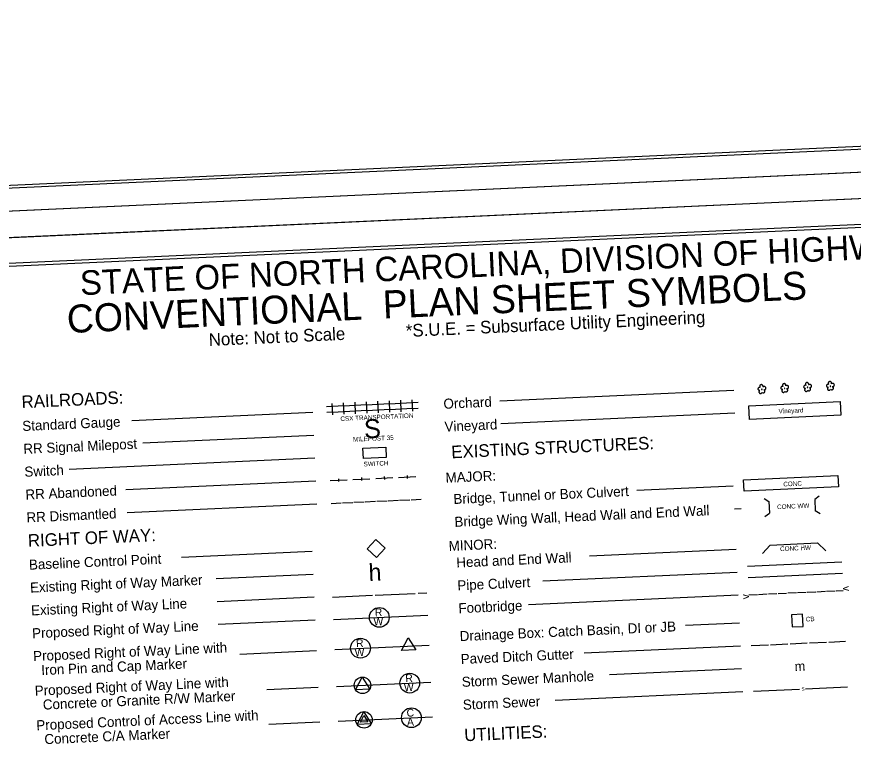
# Model space of a CAD drawing. Extents: x 1190067 to 1192950, y 891516 to 893460.
# Drawn here: x 1191359.1 to 1191651.7, y 891789.2 to 892043.5 of the extents above; entities that cross this region are included whole.
import ezdxf

# ---------------------------------------------------------------- set-up
doc = ezdxf.new("R2010")
doc.units = 0
for name, color, linetype in [('Prop Dimension Text', 7, 'Continuous'), ('Sheet Cutting Line CELL', 7, 'Continuous'), ('Sheet Plan CELL', 7, 'Continuous'), ('Sheet Plot Border Inside CELL', 7, 'Continuous'), ('Sheet Plot Border Outside CELL', 7, 'Continuous'), ('Sheet Symbology CELL', 7, 'Continuous')]:
    doc.layers.add(name, color=color, linetype=linetype)

# ---------------------------------------------------------------- blocks, each defined once
blk = doc.blocks.new('PRRM')
at = {"layer": 'Sheet Symbology CELL'}
blk.add_line((0, 0), (0, 0), dxfattribs=at)
blk.add_lwpolyline([(-0.125, -0.072), (0, 0.144), (0.125, -0.072)], close=True, dxfattribs=at)
blk = doc.blocks.new('RWCON')
at = {"layer": 'Sheet Symbology CELL'}
blk.add_line((0, 0), (0, 0), dxfattribs=at)
blk.add_lwpolyline([(-0.125, -0.072), (0, 0.144), (0.125, -0.072)], close=True, dxfattribs=at)
blk.add_circle((0, 0), 0.144, dxfattribs=at)

msp = doc.modelspace()

# ---------------------------------------------------------------- linework, layer by layer
at = {"layer": 'Prop Dimension Text'}
msp.add_lwpolyline([(1191481.72, 891857.47), (1191484.71, 891860.74), (1191487.97, 891857.76), (1191484.99, 891854.49)], close=True, dxfattribs=at)
at = {"layer": 'Sheet Cutting Line CELL'}
for p, q in [((1191133.3, 891965.4), (1191805.99, 891996.18)), ((1191806.62, 891986.81), (1191133.73, 891956.03))]:
    msp.add_line(p, q, dxfattribs=at)
at = {"layer": 'Sheet Plan CELL'}
msp.add_lwpolyline([(1191779.6, 892424.42), (1191180.22, 892397), (1191199.42, 891977.44), (1191798.79, 892004.86)], close=True, dxfattribs=at)
at = {"layer": 'Sheet Plot Border Inside CELL'}
for points in [[(1191138.13, 891973.63), (1191803.83, 892004.09), (1191784.54, 892425.65), (1191118.84, 892395.19)], [(1191158.62, 891525.69), (1191824.52, 891556.16), (1191805.24, 891977.76), (1191139.33, 891947.29)]]:
    msp.add_lwpolyline(points, close=True, dxfattribs=at)
at = {"layer": 'Sheet Plot Border Outside CELL'}
for points in [[(1191133.3, 891965.4), (1191805.99, 891996.18), (1191785.98, 892433.72), (1191113.28, 892402.94)], [(1191153.84, 891516.49), (1191826.73, 891547.27), (1191806.62, 891986.81), (1191133.73, 891956.03)]]:
    msp.add_lwpolyline(points, close=True, dxfattribs=at)
at = {"layer": 'Sheet Symbology CELL'}
for p, q in [((1191609.93, 891912.88), (1191528.04, 891909.13)), ((1191467.5, 891907.24), (1191471.5, 891907.42)), ((1191469.64, 891904.34), (1191469.46, 891908.33)), ((1191471.5, 891907.42), (1191475.5, 891907.61)), ((1191473.64, 891904.52), (1191473.45, 891908.51)), ((1191475.5, 891907.61), (1191479.49, 891907.79)), ((1191477.63, 891904.7), (1191477.45, 891908.7)), ((1191479.49, 891907.79), (1191483.49, 891907.97)), ((1191481.63, 891904.88), (1191481.44, 891908.88)), ((1191483.49, 891907.97), (1191487.48, 891908.16)), ((1191485.62, 891905.07), (1191485.44, 891909.06)), ((1191487.48, 891908.16), (1191491.48, 891908.34)), ((1191489.62, 891905.25), (1191489.44, 891909.25)), ((1191491.48, 891908.34), (1191495.48, 891908.52)), ((1191493.61, 891905.43), (1191493.43, 891909.43)), ((1191495.48, 891908.52), (1191499.47, 891908.7)), ((1191497.61, 891905.62), (1191497.43, 891909.61)), ((1191462.64, 891905.11), (1191399.34, 891902.22)), ((1191467.6, 891905.24), (1191471.59, 891905.43)), ((1191471.59, 891905.43), (1191475.59, 891905.61)), ((1191475.59, 891905.61), (1191479.58, 891905.79)), ((1191479.58, 891905.79), (1191483.58, 891905.97)), ((1191483.58, 891905.97), (1191487.58, 891906.16)), ((1191487.58, 891906.16), (1191491.57, 891906.34)), ((1191491.57, 891906.34), (1191495.57, 891906.52)), ((1191495.57, 891906.52), (1191499.56, 891906.71)), ((1191610.29, 891904.89), (1191528.4, 891901.14)), ((1191463.01, 891897.12), (1191403.25, 891894.39)), ((1191463.37, 891889.13), (1191377.5, 891885.2)), ((1191463.74, 891881.14), (1191397.34, 891878.1)), ((1191468.69, 891881.36), (1191474.68, 891881.64)), ((1191471.66, 891882), (1191471.71, 891881)), ((1191476.68, 891881.73), (1191482.67, 891882)), ((1191479.65, 891882.37), (1191479.7, 891881.37)), ((1191484.67, 891882.09), (1191490.67, 891882.37)), ((1191487.65, 891882.73), (1191487.69, 891881.73)), ((1191492.66, 891882.46), (1191498.66, 891882.73)), ((1191495.64, 891883.1), (1191495.68, 891882.1)), ((1191609.73, 891879.43), (1191576, 891877.89)), ((1191620.52, 891875.07), (1191622.21, 891874)), ((1191639.78, 891875.95), (1191638.19, 891874.73)), ((1191464.1, 891873.15), (1191397.71, 891870.11)), ((1191464.1, 891873.15), (1191397.71, 891870.11)), ((1191469.05, 891873.37), (1191472.65, 891873.54)), ((1191473.05, 891873.55), (1191476.65, 891873.72)), ((1191477.05, 891873.74), (1191480.64, 891873.9)), ((1191481.04, 891873.92), (1191484.64, 891874.09)), ((1191485.04, 891874.1), (1191488.63, 891874.27)), ((1191489.03, 891874.29), (1191492.63, 891874.45)), ((1191493.03, 891874.47), (1191496.63, 891874.63)), ((1191497.02, 891874.65), (1191500.62, 891874.82)), ((1191622.21, 891874), (1191622.39, 891870)), ((1191638.19, 891874.73), (1191638.38, 891870.73)), ((1191610.1, 891871.44), (1191612.49, 891871.55)), ((1191620.81, 891868.78), (1191622.39, 891870)), ((1191640.07, 891869.66), (1191638.38, 891870.73)), ((1191619.96, 891855.82), (1191622.66, 891858.77)), ((1191622.66, 891858.77), (1191639.14, 891859.53)), ((1191639.14, 891859.53), (1191642.1, 891856.83)), ((1191462.41, 891856.51), (1191416.77, 891854.42)), ((1191610.75, 891857.23), (1191559.48, 891854.88)), ((1191614.74, 891851.4), (1191647.7, 891852.91)), ((1191611.11, 891849.24), (1191543.11, 891846.12)), ((1191614.92, 891847.41), (1191647.88, 891848.92)), ((1191462.77, 891848.52), (1191428.83, 891846.97)), ((1191642.36, 891842.66), (1191645.36, 891842.79)), ((1191645.76, 891842.81), (1191648.16, 891842.92)), ((1191463.14, 891840.53), (1191429.2, 891838.97)), ((1191469.55, 891840.59), (1191483.54, 891841.23)), ((1191484.54, 891841.28), (1191498.52, 891841.92)), ((1191499.52, 891841.96), (1191502.52, 891842.1)), ((1191611.48, 891841.24), (1191538.16, 891837.89)), ((1191615.19, 891841.41), (1191618.19, 891841.55)), ((1191618.59, 891841.57), (1191621.59, 891841.71)), ((1191621.99, 891841.73), (1191624.98, 891841.86)), ((1191625.38, 891841.88), (1191628.38, 891842.02)), ((1191628.78, 891842.04), (1191631.78, 891842.17)), ((1191632.18, 891842.19), (1191635.17, 891842.33)), ((1191635.57, 891842.35), (1191638.57, 891842.48)), ((1191638.97, 891842.5), (1191641.96, 891842.64)), ((1191469.91, 891832.78), (1191502.88, 891834.29)), ((1191463.5, 891832.54), (1191429.56, 891830.98)), ((1191611.92, 891831.48), (1191593.06, 891830.62)), ((1191470.39, 891822.34), (1191503.35, 891823.85)), ((1191612.29, 891823.49), (1191557.57, 891820.99)), ((1191616.01, 891823.66), (1191622, 891823.94)), ((1191622.8, 891823.97), (1191628.79, 891824.25)), ((1191629.59, 891824.28), (1191635.58, 891824.56)), ((1191636.38, 891824.59), (1191642.38, 891824.87)), ((1191643.18, 891824.9), (1191648.97, 891825.17)), ((1191463.99, 891821.81), (1191437.18, 891820.58)), ((1191612.65, 891815.5), (1191566.43, 891813.38)), ((1191470.98, 891809.35), (1191503.95, 891810.86)), ((1191464.58, 891809.01), (1191446.6, 891808.18)), ((1191616.74, 891807.68), (1191632.93, 891808.42)), ((1191634.93, 891808.51), (1191649.7, 891809.19)), ((1191613.02, 891807.51), (1191547.41, 891804.51)), ((1191465.13, 891796.92), (1191447.3, 891796.1)), ((1191471.53, 891797.27), (1191504.5, 891798.78)), ((1191480.61, 891797.68), (1191480.61, 891797.68))]:
    msp.add_line(p, q, dxfattribs=at)
for points in [[(1191800.29, 891976.51), (1191200.91, 891949.09), (1191220.09, 891529.94), (1191819.46, 891557.36)], [(1191480.18, 891892.69), (1191488.17, 891893.05), (1191488.34, 891889.42), (1191480.35, 891889.05)], [(1191630.3, 891830.2), (1191634.14, 891830.37), (1191633.94, 891834.62), (1191630.1, 891834.45)], [(1191478.17, 891796.13), (1191483.17, 891796.36), (1191480.47, 891800.56)], [(1191479.33, 891796.87), (1191480.54, 891799.19), (1191481.95, 891796.99)]]:
    msp.add_lwpolyline(points, close=True, dxfattribs=at)
for points in [[(1191644.04, 891915.14), (1191644.09, 891915.26), (1191644.11, 891915.38), (1191644.08, 891915.5), (1191644.05, 891915.62), (1191643.99, 891915.72), (1191643.93, 891915.82), (1191643.82, 891915.89), (1191643.72, 891915.95), (1191643.58, 891915.98), (1191643.48, 891915.98), (1191643.36, 891915.95), (1191643.24, 891915.9), (1191643.14, 891915.84), (1191643.05, 891915.76), (1191642.99, 891915.63), (1191642.96, 891915.53), (1191642.94, 891915.41), (1191642.95, 891915.29), (1191642.97, 891915.17), (1191643.04, 891915.07), (1191643.12, 891914.96), (1191643.02, 891915.01), (1191642.9, 891915.03), (1191642.78, 891915.02), (1191642.68, 891914.98), (1191642.58, 891914.93), (1191642.49, 891914.85), (1191642.41, 891914.77), (1191642.36, 891914.66), (1191642.34, 891914.56), (1191642.33, 891914.42), (1191642.35, 891914.32), (1191642.4, 891914.22), (1191642.48, 891914.13), (1191642.55, 891914.05), (1191642.65, 891914), (1191642.77, 891913.94), (1191642.87, 891913.93), (1191642.99, 891913.93), (1191642.89, 891913.89), (1191642.8, 891913.8), (1191642.74, 891913.72), (1191642.71, 891913.6), (1191642.67, 891913.48), (1191642.68, 891913.38), (1191642.7, 891913.26), (1191642.77, 891913.16), (1191642.83, 891913.06), (1191642.91, 891912.99), (1191643.02, 891912.93), (1191643.12, 891912.9), (1191643.24, 891912.9), (1191643.36, 891912.91), (1191643.46, 891912.93), (1191643.55, 891913.02), (1191643.65, 891913.08), (1191643.74, 891913.26)], [(1191620.06, 891914.04), (1191620.12, 891914.17), (1191620.13, 891914.29), (1191620.11, 891914.41), (1191620.08, 891914.52), (1191620.02, 891914.62), (1191619.95, 891914.72), (1191619.85, 891914.79), (1191619.74, 891914.85), (1191619.6, 891914.88), (1191619.5, 891914.88), (1191619.38, 891914.85), (1191619.27, 891914.81), (1191619.17, 891914.74), (1191619.07, 891914.66), (1191619.02, 891914.54), (1191618.98, 891914.43), (1191618.97, 891914.31), (1191618.97, 891914.19), (1191619, 891914.07), (1191619.06, 891913.98), (1191619.15, 891913.86), (1191619.05, 891913.92), (1191618.93, 891913.93), (1191618.81, 891913.93), (1191618.71, 891913.88), (1191618.61, 891913.84), (1191618.51, 891913.75), (1191618.44, 891913.67), (1191618.38, 891913.57), (1191618.37, 891913.46), (1191618.35, 891913.32), (1191618.38, 891913.23), (1191618.42, 891913.13), (1191618.51, 891913.03), (1191618.57, 891912.95), (1191618.67, 891912.9), (1191618.8, 891912.84), (1191618.9, 891912.83), (1191619.02, 891912.83), (1191618.92, 891912.79), (1191618.82, 891912.7), (1191618.77, 891912.62), (1191618.73, 891912.5), (1191618.7, 891912.38), (1191618.7, 891912.28), (1191618.73, 891912.16), (1191618.79, 891912.06), (1191618.86, 891911.97), (1191618.94, 891911.89), (1191619.04, 891911.83), (1191619.14, 891911.8), (1191619.26, 891911.8), (1191619.38, 891911.81), (1191619.48, 891911.83), (1191619.58, 891911.92), (1191619.68, 891911.98), (1191619.77, 891912.17)], [(1191619.75, 891913.33), (1191619.69, 891913.33), (1191619.66, 891913.3), (1191619.62, 891913.28), (1191619.62, 891913.22), (1191619.62, 891913.18), (1191619.66, 891913.14), (1191619.72, 891913.15), (1191619.76, 891913.15), (1191619.8, 891913.19), (1191619.82, 891913.25), (1191619.8, 891913.29), (1191619.75, 891913.33)], [(1191619.77, 891912.17), (1191620.01, 891912.04), (1191620.14, 891912), (1191620.26, 891911.99), (1191620.37, 891912.02), (1191620.47, 891912.06), (1191620.57, 891912.12), (1191620.67, 891912.21), (1191620.72, 891912.31), (1191620.76, 891912.41), (1191620.79, 891912.53), (1191620.77, 891912.65), (1191620.74, 891912.77), (1191620.66, 891912.89), (1191620.59, 891912.97), (1191620.49, 891913.02), (1191620.37, 891913.08), (1191620.49, 891913.06), (1191620.63, 891913.07), (1191620.73, 891913.11), (1191620.84, 891913.18), (1191620.94, 891913.24), (1191621.01, 891913.35), (1191621.07, 891913.47), (1191621.08, 891913.59), (1191621.1, 891913.71), (1191621.07, 891913.83), (1191621.03, 891913.95), (1191620.94, 891914.04), (1191620.84, 891914.14), (1191620.74, 891914.19), (1191620.61, 891914.23), (1191620.49, 891914.24), (1191620.37, 891914.24), (1191620.26, 891914.19), (1191620.16, 891914.13), (1191620.06, 891914.04)], [(1191628.05, 891914.41), (1191628.11, 891914.53), (1191628.12, 891914.65), (1191628.1, 891914.77), (1191628.07, 891914.89), (1191628.01, 891914.99), (1191627.94, 891915.08), (1191627.84, 891915.16), (1191627.74, 891915.21), (1191627.59, 891915.25), (1191627.49, 891915.24), (1191627.38, 891915.22), (1191627.26, 891915.17), (1191627.16, 891915.11), (1191627.06, 891915.02), (1191627.01, 891914.9), (1191626.97, 891914.8), (1191626.96, 891914.68), (1191626.97, 891914.56), (1191626.99, 891914.44), (1191627.06, 891914.34), (1191627.14, 891914.23), (1191627.04, 891914.28), (1191626.92, 891914.3), (1191626.8, 891914.29), (1191626.7, 891914.25), (1191626.6, 891914.2), (1191626.51, 891914.12), (1191626.43, 891914.03), (1191626.37, 891913.93), (1191626.36, 891913.83), (1191626.34, 891913.69), (1191626.37, 891913.59), (1191626.41, 891913.49), (1191626.5, 891913.4), (1191626.56, 891913.32), (1191626.66, 891913.26), (1191626.79, 891913.21), (1191626.89, 891913.19), (1191627.01, 891913.2), (1191626.91, 891913.16), (1191626.81, 891913.07), (1191626.76, 891912.99), (1191626.72, 891912.87), (1191626.69, 891912.74), (1191626.69, 891912.64), (1191626.72, 891912.53), (1191626.78, 891912.43), (1191626.85, 891912.33), (1191626.93, 891912.26), (1191627.03, 891912.2), (1191627.14, 891912.16), (1191627.26, 891912.17), (1191627.37, 891912.18), (1191627.47, 891912.2), (1191627.57, 891912.28), (1191627.67, 891912.35), (1191627.76, 891912.53)], [(1191627.75, 891913.69), (1191627.69, 891913.69), (1191627.65, 891913.67), (1191627.61, 891913.65), (1191627.61, 891913.59), (1191627.61, 891913.55), (1191627.65, 891913.51), (1191627.71, 891913.51), (1191627.75, 891913.51), (1191627.79, 891913.56), (1191627.81, 891913.62), (1191627.79, 891913.66), (1191627.75, 891913.69)], [(1191627.76, 891912.53), (1191628.01, 891912.4), (1191628.13, 891912.37), (1191628.25, 891912.36), (1191628.37, 891912.38), (1191628.46, 891912.43), (1191628.56, 891912.49), (1191628.66, 891912.57), (1191628.71, 891912.68), (1191628.75, 891912.78), (1191628.78, 891912.9), (1191628.76, 891913.02), (1191628.73, 891913.14), (1191628.65, 891913.25), (1191628.58, 891913.33), (1191628.48, 891913.39), (1191628.36, 891913.44), (1191628.48, 891913.43), (1191628.62, 891913.43), (1191628.72, 891913.48), (1191628.83, 891913.54), (1191628.93, 891913.61), (1191629.01, 891913.71), (1191629.06, 891913.83), (1191629.08, 891913.95), (1191629.09, 891914.08), (1191629.06, 891914.19), (1191629.02, 891914.31), (1191628.93, 891914.41), (1191628.83, 891914.5), (1191628.73, 891914.56), (1191628.61, 891914.59), (1191628.48, 891914.61), (1191628.37, 891914.6), (1191628.25, 891914.56), (1191628.15, 891914.49), (1191628.05, 891914.41)], [(1191636.05, 891914.77), (1191636.1, 891914.9), (1191636.11, 891915.02), (1191636.09, 891915.14), (1191636.06, 891915.26), (1191636, 891915.35), (1191635.93, 891915.45), (1191635.83, 891915.53), (1191635.73, 891915.58), (1191635.59, 891915.61), (1191635.49, 891915.61), (1191635.37, 891915.58), (1191635.25, 891915.54), (1191635.15, 891915.47), (1191635.06, 891915.39), (1191635, 891915.27), (1191634.97, 891915.17), (1191634.95, 891915.04), (1191634.96, 891914.92), (1191634.98, 891914.81), (1191635.05, 891914.71), (1191635.13, 891914.59), (1191635.03, 891914.65), (1191634.91, 891914.66), (1191634.79, 891914.66), (1191634.69, 891914.61), (1191634.59, 891914.57), (1191634.5, 891914.48), (1191634.42, 891914.4), (1191634.37, 891914.3), (1191634.35, 891914.2), (1191634.34, 891914.06), (1191634.36, 891913.96), (1191634.41, 891913.86), (1191634.49, 891913.76), (1191634.55, 891913.68), (1191634.66, 891913.63), (1191634.78, 891913.58), (1191634.88, 891913.56), (1191635, 891913.57), (1191634.9, 891913.52), (1191634.81, 891913.44), (1191634.75, 891913.35), (1191634.71, 891913.23), (1191634.68, 891913.11), (1191634.68, 891913.01), (1191634.71, 891912.89), (1191634.77, 891912.79), (1191634.84, 891912.7), (1191634.92, 891912.62), (1191635.03, 891912.57), (1191635.13, 891912.53), (1191635.25, 891912.54), (1191635.37, 891912.54), (1191635.47, 891912.57), (1191635.56, 891912.65), (1191635.66, 891912.71), (1191635.75, 891912.9)], [(1191635.74, 891914.06), (1191635.68, 891914.06), (1191635.64, 891914.03), (1191635.6, 891914.01), (1191635.6, 891913.95), (1191635.6, 891913.91), (1191635.65, 891913.88), (1191635.71, 891913.88), (1191635.75, 891913.88), (1191635.78, 891913.92), (1191635.8, 891913.98), (1191635.78, 891914.02), (1191635.74, 891914.06)], [(1191635.75, 891912.9), (1191636, 891912.77), (1191636.12, 891912.74), (1191636.24, 891912.72), (1191636.36, 891912.75), (1191636.46, 891912.79), (1191636.55, 891912.86), (1191636.65, 891912.94), (1191636.71, 891913.04), (1191636.74, 891913.14), (1191636.77, 891913.27), (1191636.75, 891913.38), (1191636.72, 891913.5), (1191636.64, 891913.62), (1191636.58, 891913.7), (1191636.47, 891913.75), (1191636.35, 891913.81), (1191636.47, 891913.79), (1191636.61, 891913.8), (1191636.71, 891913.84), (1191636.83, 891913.91), (1191636.92, 891913.97), (1191637, 891914.08), (1191637.05, 891914.2), (1191637.07, 891914.32), (1191637.08, 891914.44), (1191637.06, 891914.56), (1191637.01, 891914.68), (1191636.93, 891914.77), (1191636.82, 891914.87), (1191636.72, 891914.93), (1191636.6, 891914.96), (1191636.48, 891914.97), (1191636.36, 891914.97), (1191636.24, 891914.92), (1191636.14, 891914.86), (1191636.05, 891914.77)], [(1191643.73, 891914.43), (1191643.67, 891914.42), (1191643.63, 891914.4), (1191643.59, 891914.38), (1191643.59, 891914.32), (1191643.6, 891914.28), (1191643.64, 891914.24), (1191643.7, 891914.24), (1191643.74, 891914.25), (1191643.78, 891914.29), (1191643.79, 891914.35), (1191643.77, 891914.39), (1191643.73, 891914.43)], [(1191643.74, 891913.26), (1191643.99, 891913.14), (1191644.11, 891913.1), (1191644.23, 891913.09), (1191644.35, 891913.11), (1191644.45, 891913.16), (1191644.55, 891913.22), (1191644.64, 891913.31), (1191644.7, 891913.41), (1191644.73, 891913.51), (1191644.77, 891913.63), (1191644.74, 891913.75), (1191644.72, 891913.87), (1191644.63, 891913.99), (1191644.57, 891914.06), (1191644.46, 891914.12), (1191644.34, 891914.17), (1191644.46, 891914.16), (1191644.6, 891914.16), (1191644.7, 891914.21), (1191644.82, 891914.27), (1191644.91, 891914.34), (1191644.99, 891914.44), (1191645.04, 891914.57), (1191645.06, 891914.69), (1191645.07, 891914.81), (1191645.05, 891914.93), (1191645, 891915.04), (1191644.92, 891915.14), (1191644.81, 891915.24), (1191644.71, 891915.29), (1191644.59, 891915.33), (1191644.47, 891915.34), (1191644.35, 891915.33), (1191644.23, 891915.29), (1191644.13, 891915.22), (1191644.04, 891915.14)], [(1191615.14, 891907.51), (1191647.1, 891908.97), (1191647.32, 891904.18), (1191615.35, 891902.72), (1191615.14, 891907.51)], [(1191613.35, 891881.6), (1191646.32, 891883.11), (1191646.5, 891879.11), (1191613.54, 891877.6), (1191613.35, 891881.6)]]:
    msp.add_lwpolyline(points, dxfattribs=at)
for centre, radius in [((1191485.94, 891833.51), 3.45), ((1191479.35, 891822.75), 3.45), ((1191496.59, 891810.52), 3.45), ((1191497.15, 891798.44), 3.45), ((1191480.6, 891797.68), 2.88)]:
    msp.add_circle(centre, radius, dxfattribs=at)

# ---------------------------------------------------------------- block references
at = {"layer": 'Prop Dimension Text', "xscale": 20.000000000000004, "yscale": 20, "rotation": 2.619466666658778}
for name, p in [('PRRM', (1191496.14, 891823.52)), ('RWCON', (1191480.05, 891809.77))]:
    msp.add_blockref(name, p, dxfattribs=at)

# ---------------------------------------------------------------- texts
at = {"layer": 'Sheet Symbology CELL'}
for s, height, rotation, p in [('STATE OF NORTH CAROLINA, DIVISION OF HIGHWAYS', 8.5676, 2.6195, (1191381.46, 891946.15)), ('CONVENTIONAL  PLAN SHEET SYMBOLS', 9.7921, 2.6195, (1191376.88, 891932.9)), ('*S.U.E. = Subsurface Utility Engineering', 4.4, 2.6195, (1191495.31, 891931.53)), ('Note: Not to Scale', 4.4, 2.6195, (1191426.39, 891928.38)), ('RAILROADS:', 4.4, 2.6195, (1191360.91, 891906.64)), ('Orchard', 3.5, 2.6195, (1191508.45, 891906.42)), ('CSX TRANSPORTATION', 1.6, 2.6195, (1191472.37, 891902.16)), ('Vineyard', 1.6, 2.6195, (1191625.6, 891904.79)), ('Standard Gauge', 3.5, 2.6195, (1191361.16, 891898.66)), ('S', 6.6, 2.6195, (1191480.73, 891896.08)), ('Vineyard', 3.5, 2.6195, (1191508.82, 891898.43)), ('RR Signal Milepost', 3.5, 2.6195, (1191361.53, 891890.67)), ('MILEPOST 35', 1.6, 2.6195, (1191476.78, 891894.93)), ('EXISTING STRUCTURES:', 4.4, 2.6195, (1191511.2, 891889.12)), ('Switch', 3.5, 2.6195, (1191361.89, 891882.67)), ('SWITCH', 1.6, 2.6195, (1191480.46, 891886.29)), ('MAJOR:', 3.5, 2.6195, (1191509.18, 891880.57)), ('CONC', 1.6, 2.6195, (1191627.25, 891879.29)), ('RR Abandoned', 3.5, 2.6195, (1191362.26, 891874.68)), ('Bridge, Tunnel or Box Culvert', 3.5, 2.6195, (1191511.93, 891873.14)), ('Bridge Wing Wall, Head Wall and End Wall', 3.5, 2.6195, (1191512.3, 891865.14)), ('CONC WW', 1.6, 2.6195, (1191625.09, 891871.33)), ('RR Dismantled', 3.5, 2.6195, (1191362.63, 891866.69)), ('RIGHT OF WAY:', 4.4, 2.6195, (1191363.13, 891858.15)), ('MINOR:', 3.5, 2.6195, (1191510.27, 891856.72)), ('CONC HW', 1.6, 2.6195, (1191626.13, 891856.67)), ('Baseline Control Point', 3.5, 2.6195, (1191363.49, 891850.16)), ('Head and End Wall', 3.5, 2.6195, (1191512.95, 891850.93)), ('h', 6, 2.6195, (1191482.32, 891846.18)), ('Existing Right of Way Marker', 3.5, 2.6195, (1191363.86, 891842.17)), ('Pipe Culvert', 3.5, 2.6195, (1191513.31, 891842.94)), ('v', 2.64, 272.8603, (1191648.09, 891844.42)), ('Existing Right of Way Line', 3.5, 2.6195, (1191364.22, 891834.18)), ('v', 2.64, 92.3786, (1191615.26, 891839.92)), ('Footbridge', 3.5, 2.6195, (1191513.68, 891834.95)), ('R', 2.7, 2.6195, (1191484.44, 891833.85)), ('Proposed Right of Way Line', 3.5, 2.6195, (1191364.59, 891826.19)), ('W', 2.7, 2.6195, (1191483.97, 891830.64)), ('Drainage Box: Catch Basin, DI or JB', 3.5, 2.6195, (1191514.13, 891825.19)), ('CB', 1.6, 2.6195, (1191635.12, 891832.07)), ('R', 2.7, 2.6195, (1191477.85, 891823.09)), ('Proposed Right of Way Line with', 3.5, 2.6195, (1191364.95, 891818.2)), ('W', 2.7, 2.6195, (1191477.38, 891819.88)), ('Paved Ditch Gutter', 3.5, 2.6195, (1191514.49, 891817.19)), ('  Iron Pin and Cap Marker', 3.5, 2.6195, (1191365.18, 891813.2)), ('m', 3.3, 2.6195, (1191631.28, 891814.7)), ('R', 2.7, 2.6195, (1191495.09, 891810.86)), ('Storm Sewer Manhole', 3.5, 2.6195, (1191514.86, 891809.2)), ('Proposed Right of Way Line with', 3.5, 2.6195, (1191365.51, 891806.12)), ('  Concrete or Granite R/W Marker', 3.5, 2.6195, (1191365.74, 891801.12)), ('W', 2.7, 2.6195, (1191494.62, 891807.66)), ('S', 1.2, 2.6195, (1191633.6, 891807.85)), ('Storm Sewer', 3.5, 2.6195, (1191515.23, 891801.21)), ('Proposed Control of Access Line with', 3.5, 2.6195, (1191366.06, 891794.03)), ('C', 2.7, 2.6195, (1191495.54, 891798.77)), ('A', 2.7, 2.6195, (1191495.67, 891795.59)), ('  Concrete C/A Marker', 3.5, 2.6195, (1191366.29, 891789.04)), ('UTILITIES:', 4.4, 2.6195, (1191515.73, 891790.19))]:
    msp.add_text(s, height=height, rotation=rotation, dxfattribs=at).set_placement(p)

doc.saveas('drawing.dxf')
